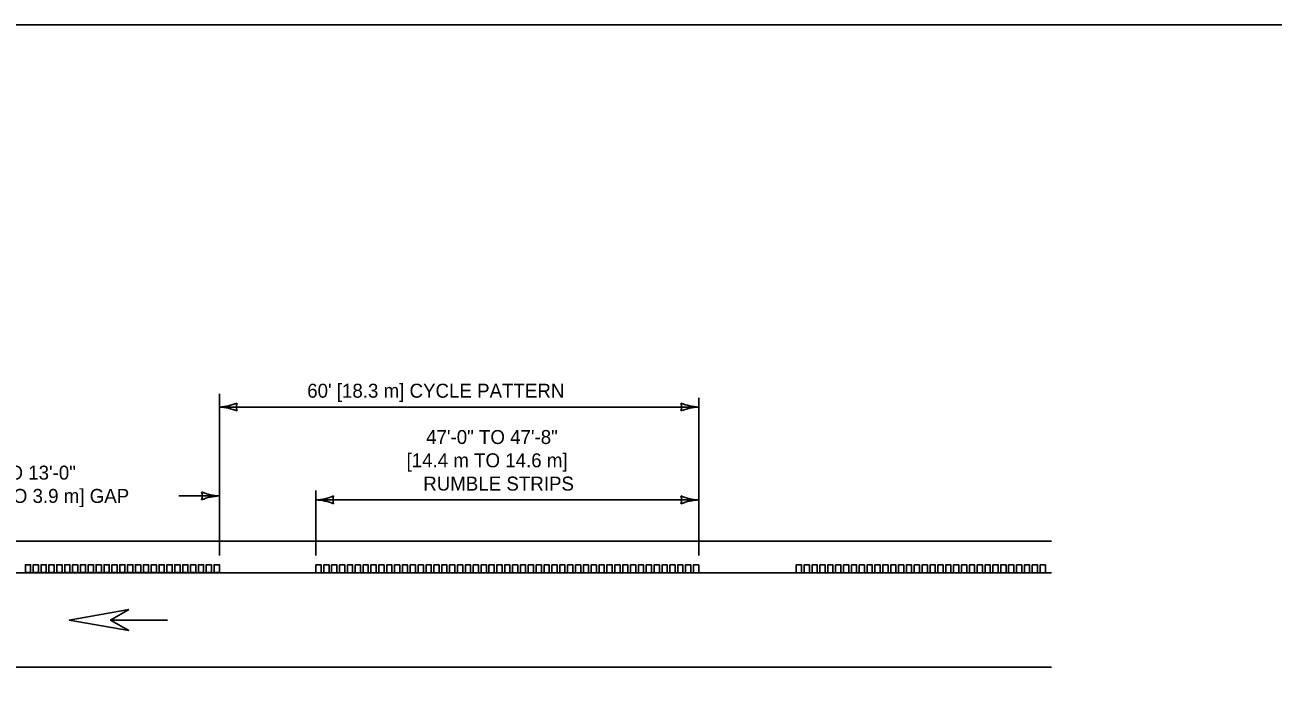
# Model space of a CAD drawing. Extents: x 49991.4 to 50021, y 49987.6 to 50011.4.
# Drawn here: x 50003.18 to 50008.54, y 49996.19 to 49999 of the extents above; entities that cross this region are included whole.
import ezdxf

# ---------------------------------------------------------------- set-up
doc = ezdxf.new("R2010")
doc.units = 0
for name, color, linetype in [('Level 1', 7, 'Continuous'), ('Level 2', 7, 'Continuous'), ('Level 3', 7, 'Continuous')]:
    doc.layers.add(name, color=color, linetype=linetype)

msp = doc.modelspace()

# ---------------------------------------------------------------- linework, layer by layer
at = {"layer": 'Level 1'}
for p, q in [((50007.5892, 49996.7823), (50001.3657, 49996.7823)), ((50007.5892, 49996.6473), (50001.3657, 49996.6473)), ((50003.796, 49996.4442), (50003.5521, 49996.4442)), ((50003.796, 49996.4439), (50003.5521, 49996.4439)), ((50007.5892, 49996.2423), (50001.3657, 49996.2423))]:
    msp.add_line(p, q, dxfattribs=at)
for points in [[(49999.3835, 49998.9992), (50016.7501, 49998.9992), (50016.7501, 49987.7988), (49999.3835, 49987.7988)], [(50003.1865, 49996.6475), (50003.2089, 49996.6475), (50003.2089, 49996.6812), (50003.1865, 49996.6812)], [(50003.2203, 49996.6475), (50003.2427, 49996.6475), (50003.2427, 49996.6812), (50003.2203, 49996.6812)], [(50003.254, 49996.6475), (50003.2764, 49996.6475), (50003.2764, 49996.6812), (50003.254, 49996.6812)], [(50003.2877, 49996.6475), (50003.3101, 49996.6475), (50003.3101, 49996.6812), (50003.2877, 49996.6812)], [(50003.3215, 49996.6475), (50003.3439, 49996.6475), (50003.3439, 49996.6812), (50003.3215, 49996.6812)], [(50003.3553, 49996.6475), (50003.3777, 49996.6475), (50003.3777, 49996.6812), (50003.3553, 49996.6812)], [(50003.389, 49996.6475), (50003.4114, 49996.6475), (50003.4114, 49996.6812), (50003.389, 49996.6812)], [(50003.4227, 49996.6475), (50003.4451, 49996.6475), (50003.4451, 49996.6812), (50003.4227, 49996.6812)], [(50003.4565, 49996.6475), (50003.4789, 49996.6475), (50003.4789, 49996.6812), (50003.4565, 49996.6812)], [(50003.4903, 49996.6475), (50003.5127, 49996.6475), (50003.5127, 49996.6812), (50003.4903, 49996.6812)], [(50003.524, 49996.6475), (50003.5464, 49996.6475), (50003.5464, 49996.6812), (50003.524, 49996.6812)], [(50003.5577, 49996.6475), (50003.5801, 49996.6475), (50003.5801, 49996.6812), (50003.5577, 49996.6812)], [(50003.5915, 49996.6475), (50003.6139, 49996.6475), (50003.6139, 49996.6812), (50003.5915, 49996.6812)], [(50003.6253, 49996.6475), (50003.6477, 49996.6475), (50003.6477, 49996.6812), (50003.6253, 49996.6812)], [(50003.659, 49996.6475), (50003.6814, 49996.6475), (50003.6814, 49996.6812), (50003.659, 49996.6812)], [(50003.6927, 49996.6475), (50003.7151, 49996.6475), (50003.7151, 49996.6812), (50003.6927, 49996.6812)], [(50003.7265, 49996.6475), (50003.7489, 49996.6475), (50003.7489, 49996.6812), (50003.7265, 49996.6812)], [(50003.7603, 49996.6475), (50003.7827, 49996.6475), (50003.7827, 49996.6812), (50003.7603, 49996.6812)], [(50003.794, 49996.6475), (50003.8164, 49996.6475), (50003.8164, 49996.6812), (50003.794, 49996.6812)], [(50003.8277, 49996.6475), (50003.8501, 49996.6475), (50003.8501, 49996.6812), (50003.8277, 49996.6812)], [(50003.8615, 49996.6475), (50003.8839, 49996.6475), (50003.8839, 49996.6812), (50003.8615, 49996.6812)], [(50003.8953, 49996.6475), (50003.9177, 49996.6475), (50003.9177, 49996.6812), (50003.8953, 49996.6812)], [(50003.929, 49996.6475), (50003.9514, 49996.6475), (50003.9514, 49996.6812), (50003.929, 49996.6812)], [(50003.9627, 49996.6475), (50003.9851, 49996.6475), (50003.9851, 49996.6812), (50003.9627, 49996.6812)], [(50003.9965, 49996.6475), (50004.0189, 49996.6475), (50004.0189, 49996.6812), (50003.9965, 49996.6812)], [(50004.4331, 49996.6474), (50004.4555, 49996.6474), (50004.4555, 49996.6811), (50004.4331, 49996.6811)], [(50004.4669, 49996.6474), (50004.4893, 49996.6474), (50004.4893, 49996.6811), (50004.4669, 49996.6811)], [(50004.5006, 49996.6474), (50004.523, 49996.6474), (50004.523, 49996.6811), (50004.5006, 49996.6811)], [(50004.5343, 49996.6474), (50004.5567, 49996.6474), (50004.5567, 49996.6811), (50004.5343, 49996.6811)], [(50004.5681, 49996.6474), (50004.5905, 49996.6474), (50004.5905, 49996.6811), (50004.5681, 49996.6811)], [(50004.6019, 49996.6474), (50004.6243, 49996.6474), (50004.6243, 49996.6811), (50004.6019, 49996.6811)], [(50004.6356, 49996.6474), (50004.658, 49996.6474), (50004.658, 49996.6811), (50004.6356, 49996.6811)], [(50004.6693, 49996.6474), (50004.6917, 49996.6474), (50004.6917, 49996.6811), (50004.6693, 49996.6811)], [(50004.7031, 49996.6474), (50004.7255, 49996.6474), (50004.7255, 49996.6811), (50004.7031, 49996.6811)], [(50004.7369, 49996.6474), (50004.7593, 49996.6474), (50004.7593, 49996.6811), (50004.7369, 49996.6811)], [(50004.7706, 49996.6474), (50004.793, 49996.6474), (50004.793, 49996.6811), (50004.7706, 49996.6811)], [(50004.8043, 49996.6474), (50004.8267, 49996.6474), (50004.8267, 49996.6811), (50004.8043, 49996.6811)], [(50004.8381, 49996.6474), (50004.8605, 49996.6474), (50004.8605, 49996.6811), (50004.8381, 49996.6811)], [(50004.8719, 49996.6474), (50004.8943, 49996.6474), (50004.8943, 49996.6811), (50004.8719, 49996.6811)], [(50004.9056, 49996.6474), (50004.928, 49996.6474), (50004.928, 49996.6811), (50004.9056, 49996.6811)], [(50004.9393, 49996.6474), (50004.9617, 49996.6474), (50004.9617, 49996.6811), (50004.9393, 49996.6811)], [(50004.9731, 49996.6474), (50004.9955, 49996.6474), (50004.9955, 49996.6811), (50004.9731, 49996.6811)], [(50005.0069, 49996.6474), (50005.0293, 49996.6474), (50005.0293, 49996.6811), (50005.0069, 49996.6811)], [(50005.0406, 49996.6474), (50005.063, 49996.6474), (50005.063, 49996.6811), (50005.0406, 49996.6811)], [(50005.0743, 49996.6474), (50005.0967, 49996.6474), (50005.0967, 49996.6811), (50005.0743, 49996.6811)], [(50005.1081, 49996.6474), (50005.1305, 49996.6474), (50005.1305, 49996.6811), (50005.1081, 49996.6811)], [(50005.1419, 49996.6474), (50005.1643, 49996.6474), (50005.1643, 49996.6811), (50005.1419, 49996.6811)], [(50005.1756, 49996.6474), (50005.198, 49996.6474), (50005.198, 49996.6811), (50005.1756, 49996.6811)], [(50005.2093, 49996.6474), (50005.2317, 49996.6474), (50005.2317, 49996.6811), (50005.2093, 49996.6811)], [(50005.2431, 49996.6474), (50005.2655, 49996.6474), (50005.2655, 49996.6811), (50005.2431, 49996.6811)], [(50005.2769, 49996.6474), (50005.2993, 49996.6474), (50005.2993, 49996.6811), (50005.2769, 49996.6811)], [(50005.3106, 49996.6474), (50005.333, 49996.6474), (50005.333, 49996.6811), (50005.3106, 49996.6811)], [(50005.3443, 49996.6474), (50005.3667, 49996.6474), (50005.3667, 49996.6811), (50005.3443, 49996.6811)], [(50005.3781, 49996.6474), (50005.4005, 49996.6474), (50005.4005, 49996.6811), (50005.3781, 49996.6811)], [(50005.4119, 49996.6474), (50005.4343, 49996.6474), (50005.4343, 49996.6811), (50005.4119, 49996.6811)], [(50005.4456, 49996.6474), (50005.468, 49996.6474), (50005.468, 49996.6811), (50005.4456, 49996.6811)], [(50005.4793, 49996.6474), (50005.5017, 49996.6474), (50005.5017, 49996.6811), (50005.4793, 49996.6811)], [(50005.5131, 49996.6474), (50005.5355, 49996.6474), (50005.5355, 49996.6811), (50005.5131, 49996.6811)], [(50005.5469, 49996.6474), (50005.5693, 49996.6474), (50005.5693, 49996.6811), (50005.5469, 49996.6811)], [(50005.5806, 49996.6474), (50005.603, 49996.6474), (50005.603, 49996.6811), (50005.5806, 49996.6811)], [(50005.6143, 49996.6474), (50005.6367, 49996.6474), (50005.6367, 49996.6811), (50005.6143, 49996.6811)], [(50005.6481, 49996.6474), (50005.6705, 49996.6474), (50005.6705, 49996.6811), (50005.6481, 49996.6811)], [(50005.6819, 49996.6474), (50005.7043, 49996.6474), (50005.7043, 49996.6811), (50005.6819, 49996.6811)], [(50005.7156, 49996.6474), (50005.738, 49996.6474), (50005.738, 49996.6811), (50005.7156, 49996.6811)], [(50005.7493, 49996.6474), (50005.7717, 49996.6474), (50005.7717, 49996.6811), (50005.7493, 49996.6811)], [(50005.7831, 49996.6474), (50005.8055, 49996.6474), (50005.8055, 49996.6811), (50005.7831, 49996.6811)], [(50005.8169, 49996.6474), (50005.8393, 49996.6474), (50005.8393, 49996.6811), (50005.8169, 49996.6811)], [(50005.8506, 49996.6474), (50005.873, 49996.6474), (50005.873, 49996.6811), (50005.8506, 49996.6811)], [(50005.8843, 49996.6474), (50005.9067, 49996.6474), (50005.9067, 49996.6811), (50005.8843, 49996.6811)], [(50005.9181, 49996.6474), (50005.9405, 49996.6474), (50005.9405, 49996.6811), (50005.9181, 49996.6811)], [(50005.9519, 49996.6474), (50005.9743, 49996.6474), (50005.9743, 49996.6811), (50005.9519, 49996.6811)], [(50005.9856, 49996.6474), (50006.008, 49996.6474), (50006.008, 49996.6811), (50005.9856, 49996.6811)], [(50006.0193, 49996.6474), (50006.0417, 49996.6474), (50006.0417, 49996.6811), (50006.0193, 49996.6811)], [(50006.0531, 49996.6474), (50006.0755, 49996.6474), (50006.0755, 49996.6811), (50006.0531, 49996.6811)], [(50006.4941, 49996.6474), (50006.5165, 49996.6474), (50006.5165, 49996.6811), (50006.4941, 49996.6811)], [(50006.5279, 49996.6474), (50006.5503, 49996.6474), (50006.5503, 49996.6811), (50006.5279, 49996.6811)], [(50006.5616, 49996.6474), (50006.584, 49996.6474), (50006.584, 49996.6811), (50006.5616, 49996.6811)], [(50006.5953, 49996.6474), (50006.6177, 49996.6474), (50006.6177, 49996.6811), (50006.5953, 49996.6811)], [(50006.6291, 49996.6474), (50006.6515, 49996.6474), (50006.6515, 49996.6811), (50006.6291, 49996.6811)], [(50006.6629, 49996.6474), (50006.6853, 49996.6474), (50006.6853, 49996.6811), (50006.6629, 49996.6811)], [(50006.6966, 49996.6474), (50006.719, 49996.6474), (50006.719, 49996.6811), (50006.6966, 49996.6811)], [(50006.7303, 49996.6474), (50006.7527, 49996.6474), (50006.7527, 49996.6811), (50006.7303, 49996.6811)], [(50006.7641, 49996.6474), (50006.7865, 49996.6474), (50006.7865, 49996.6811), (50006.7641, 49996.6811)], [(50006.7979, 49996.6474), (50006.8203, 49996.6474), (50006.8203, 49996.6811), (50006.7979, 49996.6811)], [(50006.8316, 49996.6474), (50006.854, 49996.6474), (50006.854, 49996.6811), (50006.8316, 49996.6811)], [(50006.8653, 49996.6474), (50006.8877, 49996.6474), (50006.8877, 49996.6811), (50006.8653, 49996.6811)], [(50006.8991, 49996.6474), (50006.9215, 49996.6474), (50006.9215, 49996.6811), (50006.8991, 49996.6811)], [(50006.9329, 49996.6474), (50006.9553, 49996.6474), (50006.9553, 49996.6811), (50006.9329, 49996.6811)], [(50006.9666, 49996.6474), (50006.989, 49996.6474), (50006.989, 49996.6811), (50006.9666, 49996.6811)], [(50007.0003, 49996.6474), (50007.0227, 49996.6474), (50007.0227, 49996.6811), (50007.0003, 49996.6811)], [(50007.0341, 49996.6474), (50007.0565, 49996.6474), (50007.0565, 49996.6811), (50007.0341, 49996.6811)], [(50007.0679, 49996.6474), (50007.0903, 49996.6474), (50007.0903, 49996.6811), (50007.0679, 49996.6811)], [(50007.1016, 49996.6474), (50007.124, 49996.6474), (50007.124, 49996.6811), (50007.1016, 49996.6811)], [(50007.1353, 49996.6474), (50007.1577, 49996.6474), (50007.1577, 49996.6811), (50007.1353, 49996.6811)], [(50007.1691, 49996.6474), (50007.1915, 49996.6474), (50007.1915, 49996.6811), (50007.1691, 49996.6811)], [(50007.2029, 49996.6474), (50007.2253, 49996.6474), (50007.2253, 49996.6811), (50007.2029, 49996.6811)], [(50007.2366, 49996.6474), (50007.259, 49996.6474), (50007.259, 49996.6811), (50007.2366, 49996.6811)], [(50007.2703, 49996.6474), (50007.2927, 49996.6474), (50007.2927, 49996.6811), (50007.2703, 49996.6811)], [(50007.3041, 49996.6474), (50007.3265, 49996.6474), (50007.3265, 49996.6811), (50007.3041, 49996.6811)], [(50007.3379, 49996.6474), (50007.3603, 49996.6474), (50007.3603, 49996.6811), (50007.3379, 49996.6811)], [(50007.3716, 49996.6474), (50007.394, 49996.6474), (50007.394, 49996.6811), (50007.3716, 49996.6811)], [(50007.4053, 49996.6474), (50007.4277, 49996.6474), (50007.4277, 49996.6811), (50007.4053, 49996.6811)], [(50007.4391, 49996.6474), (50007.4615, 49996.6474), (50007.4615, 49996.6811), (50007.4391, 49996.6811)], [(50007.4729, 49996.6474), (50007.4953, 49996.6474), (50007.4953, 49996.6811), (50007.4729, 49996.6811)], [(50007.5067, 49996.6474), (50007.5291, 49996.6474), (50007.5291, 49996.6811), (50007.5067, 49996.6811)], [(50007.5404, 49996.6474), (50007.5628, 49996.6474), (50007.5628, 49996.6811), (50007.5404, 49996.6811)], [(50003.6301, 49996.4892), (50003.3745, 49996.4442), (50003.6301, 49996.3989), (50003.5521, 49996.4442)]]:
    msp.add_lwpolyline(points, close=True, dxfattribs=at)
at = {"layer": 'Level 3'}
for p, q in [((50004.0189, 49997.4158), (50004.0189, 49996.7212)), ((50006.0755, 49997.3987), (50006.0755, 49996.7211)), ((50004.0189, 49997.3587), (50006.0755, 49997.3587)), ((50004.4331, 49996.9999), (50004.4331, 49996.7211)), ((50003.8455, 49996.977), (50004.0189, 49996.977)), ((50004.4331, 49996.9599), (50006.0755, 49996.9599))]:
    msp.add_line(p, q, dxfattribs=at)
for centre, radius, start, end in [((50004.0074, 49997.5914), 0.233, 272.8273, 292.0772), ((50004.1471, 49997.3587), 0.0548, 162.1388, 197.8612), ((50006.0847, 49997.5808), 0.2223, 247.456, 267.6395), ((50005.9473, 49997.3587), 0.0548, 342.1388, 17.8612), ((50004.0098, 49997.1365), 0.2223, 67.456, 87.6395), ((50006.087, 49997.1259), 0.233, 92.8273, 112.0772), ((50004.0281, 49997.1992), 0.2223, 247.456, 267.6395), ((50003.8907, 49996.977), 0.0548, 342.1388, 17.8612), ((50004.0304, 49996.7443), 0.233, 92.8273, 112.0772), ((50004.4216, 49997.1926), 0.233, 272.8273, 292.0772), ((50004.424, 49996.7378), 0.2223, 67.456, 87.6395), ((50004.5614, 49996.9599), 0.0548, 162.1388, 197.8612), ((50006.0847, 49997.182), 0.2223, 247.456, 267.6395), ((50005.9473, 49996.9599), 0.0548, 342.1388, 17.8612), ((50006.087, 49996.7272), 0.233, 92.8273, 112.0772)]:
    msp.add_arc(centre, radius, start, end, dxfattribs=at)

# ---------------------------------------------------------------- texts
at = {"layer": 'Level 2'}
for s, p in [("60' [18.3 m] CYCLE PATTERN", (50004.3958, 49997.3987)), ('47\'-0" TO 47\'-8"', (50004.906, 49997.1999)), ('[14.4 m TO 14.6 m]', (50004.8218, 49997.0999)), ('RUMBLE STRIPS', (50004.8936, 49996.9999))]:
    msp.add_text(s, height=0.06, rotation=0.0001, dxfattribs=at).set_placement(p)
for s, p in [('12\'-4" TO 13\'-0"', (50002.8384, 49997.047)), ('[3.7 m TO 3.9 m] GAP', (50002.8384, 49996.947))]:
    msp.add_text(s, height=0.06, dxfattribs=at).set_placement(p)

doc.saveas('drawing.dxf')
